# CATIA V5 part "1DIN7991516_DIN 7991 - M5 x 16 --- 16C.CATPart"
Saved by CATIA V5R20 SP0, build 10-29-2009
Part number: 1DIN7991516_DIN 7991 - M5 x 16 --- 16C
Revision: ANY
Definition: UNKNOWN
Nomenclature: 1DIN7991516_DIN 7991 - M5 x 16 --- 16C
Source: Unknown
Bounding box of the stored display mesh (mm): x 0 to 16, y -4.82 to 4.82, z -4.82 to 4.82
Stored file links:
  C:\Users\Utente\Desktop\IO LAVORO\3D X SITO CF\CUMSA\3D files RC\RC 123006\1DIN7991516_DIN 7991 - M5 x 16 --- 16C.CATPart
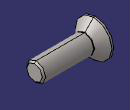
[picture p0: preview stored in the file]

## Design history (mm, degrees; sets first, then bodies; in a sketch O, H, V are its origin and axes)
Body1 "Hex" (main body)
  Solid1: solid without history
